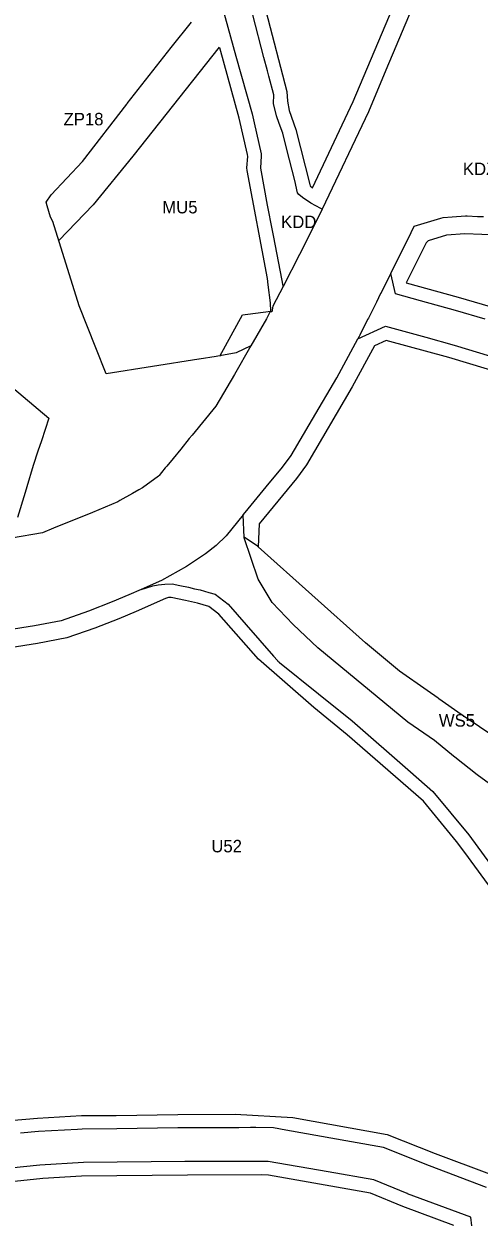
# Model space of a CAD drawing. Extents: x 7428103 to 7431580, y 5545880 to 5549002.
# Drawn here: x 7430015 to 7430217, y 5547123 to 5547655 of the extents above; entities that cross this region are included whole.
import ezdxf

# ---------------------------------------------------------------- set-up
doc = ezdxf.new("R2010")
doc.units = 0
for name, color, linetype in [('CZ_L_linie rozgraniczające tereny o różnym przeznaczeniu oraz różnych warunkach ich zabudowy i zagospodarowania', 7, 'Continuous'), ('CZ_L_maksymalne nieprzekraczalne linie zabudowy', 7, 'Continuous'), ('CZ_L_opisy_linie rozgraniczające tereny o różnym przeznaczeniu oraz różnych warunkach ich zabudowy i zagospodarowania', 7, 'Continuous')]:
    doc.layers.add(name, color=color, linetype=linetype)

msp = doc.modelspace()

# ---------------------------------------------------------------- linework, layer by layer
at = {"layer": 'CZ_L_linie rozgraniczające tereny o różnym przeznaczeniu oraz różnych warunkach ich zabudowy i zagospodarowania'}
for p, q in [((7430103.34, 5547662.02), (7430109.29, 5547640.69)), ((7430121.68, 5547640.08), (7430116.77, 5547658.97)), ((7430187.6, 5547662.03), (7430175.91, 5547634.4)), ((7430080.55, 5547644.47), (7430089.49, 5547655.67)), ((7430060.95, 5547619.6), (7430080.55, 5547644.47)), ((7430109.29, 5547640.69), (7430116.44, 5547615.02)), ((7430123.26, 5547634.11), (7430121.68, 5547640.08)), ((7430123.88, 5547631.75), (7430123.26, 5547634.11)), ((7430126.06, 5547623.49), (7430123.88, 5547631.75)), ((7430175.91, 5547634.4), (7430168.1, 5547615.94)), ((7430126, 5547619.68), (7430126.06, 5547623.49)), ((7430041.12, 5547593.87), (7430060.77, 5547619.36)), ((7430060.77, 5547619.36), (7430060.95, 5547619.6)), ((7430127.35, 5547614.15), (7430126, 5547619.68)), ((7430168.1, 5547615.94), (7430147.61, 5547572.74)), ((7430116.44, 5547615.02), (7430117.37, 5547610.98)), ((7430117.37, 5547610.98), (7430120.5, 5547597.34)), ((7430128.55, 5547610.79), (7430127.35, 5547614.15)), ((7430130.09, 5547606.41), (7430128.55, 5547610.79)), ((7430131.91, 5547599.26), (7430130.09, 5547606.41)), ((7430120.55, 5547596.45), (7430120.13, 5547590.86)), ((7430120.5, 5547597.34), (7430120.43, 5547596.99)), ((7430120.43, 5547596.99), (7430120.43, 5547596.97)), ((7430120.43, 5547596.97), (7430120.44, 5547596.97)), ((7430120.44, 5547596.97), (7430120.55, 5547596.45)), ((7430135.41, 5547585.48), (7430131.91, 5547599.26)), ((7430027.24, 5547579.08), (7430041.12, 5547593.87)), ((7430120.13, 5547590.86), (7430123.18, 5547574.5)), ((7430136.6, 5547579.96), (7430135.41, 5547585.48)), ((7430024.98, 5547575.82), (7430027.24, 5547579.08)), ((7430137.18, 5547579.26), (7430136.6, 5547579.96)), ((7430138.87, 5547577.91), (7430137.18, 5547579.26)), ((7430025.43, 5547574.25), (7430024.98, 5547575.82)), ((7430026.89, 5547569.16), (7430025.43, 5547574.25)), ((7430123.18, 5547574.5), (7430125.32, 5547563.31)), ((7430142.5, 5547575.41), (7430138.87, 5547577.91)), ((7430147.03, 5547573.05), (7430142.5, 5547575.41)), ((7430147.61, 5547572.74), (7430147.03, 5547573.05)), ((7430027.94, 5547567.27), (7430026.89, 5547569.16)), ((7430147.52, 5547572.56), (7430137.52, 5547552.62)), ((7430147.61, 5547572.74), (7430147.52, 5547572.56)), ((7430188.51, 5547565.14), (7430200.32, 5547568.75)), ((7430200.32, 5547568.75), (7430201.34, 5547569.08)), ((7430201.34, 5547569.08), (7430205.32, 5547569.36)), ((7430205.32, 5547569.36), (7430211.26, 5547569.73)), ((7430211.26, 5547569.73), (7430212.04, 5547569.7)), ((7430212.04, 5547569.7), (7430216.64, 5547569.5)), ((7430216.64, 5547569.5), (7430219.19, 5547569.4)), ((7430039.57, 5547529.77), (7430027.94, 5547567.27)), ((7430125.32, 5547563.31), (7430125.77, 5547561.01)), ((7430178.06, 5547544.23), (7430187.15, 5547562.35)), ((7430187.15, 5547562.35), (7430188.51, 5547565.14)), ((7430125.77, 5547561.01), (7430129.64, 5547541.1)), ((7430137.52, 5547552.62), (7430130.18, 5547538.32)), ((7430129.64, 5547541.1), (7430129.98, 5547539.37)), ((7430177.64, 5547543.39), (7430173.59, 5547535.33)), ((7430178.06, 5547544.23), (7430177.64, 5547543.39)), ((7430180.09, 5547535.11), (7430178.06, 5547544.23)), ((7430130.18, 5547538.32), (7430125.71, 5547529.6)), ((7430129.98, 5547539.37), (7430130.18, 5547538.32)), ((7430171.64, 5547531.43), (7430168.11, 5547524.39)), ((7430173.55, 5547535.24), (7430171.64, 5547531.43)), ((7430173.59, 5547535.33), (7430173.55, 5547535.24)), ((7430191.32, 5547532.04), (7430180.09, 5547535.11)), ((7430206.84, 5547527.79), (7430191.32, 5547532.04)), ((7430047, 5547511.09), (7430039.57, 5547529.77)), ((7430124.37, 5547527), (7430122.85, 5547524.03)), ((7430125.28, 5547527.15), (7430124.37, 5547527)), ((7430125.71, 5547529.6), (7430125.28, 5547527.15)), ((7430220.04, 5547523.9), (7430206.84, 5547527.79)), ((7430122.85, 5547524.03), (7430115.96, 5547512.09)), ((7430163.44, 5547515.23), (7430175.64, 5547520.78)), ((7430167.77, 5547523.72), (7430164.31, 5547516.82)), ((7430168.11, 5547524.39), (7430167.77, 5547523.72)), ((7430175.64, 5547520.78), (7430193.68, 5547515.84)), ((7429985, 5547514.47), (7430026.23, 5547479.99)), ((7430154.02, 5547497.86), (7430163.44, 5547515.23)), ((7430164, 5547516.25), (7430163.44, 5547515.23)), ((7430164.31, 5547516.82), (7430164, 5547516.25)), ((7430193.68, 5547515.84), (7430206.19, 5547512.39)), ((7430051.58, 5547499.58), (7430047, 5547511.09)), ((7430115.96, 5547512.09), (7430108.59, 5547499.31)), ((7430115.96, 5547512.09), (7430109.32, 5547508.89)), ((7430206.19, 5547512.39), (7430222.42, 5547507.51)), ((7430092.83, 5547506.16), (7430051.58, 5547499.58)), ((7430092.85, 5547506.17), (7430092.83, 5547506.16)), ((7430092.89, 5547506.15), (7430092.85, 5547506.17)), ((7430092.92, 5547506.17), (7430092.89, 5547506.15)), ((7430100.5, 5547507.35), (7430092.92, 5547506.17)), ((7430109.32, 5547508.89), (7430100.5, 5547507.35)), ((7430108.59, 5547499.31), (7430100.29, 5547485.2)), ((7430143.31, 5547479.44), (7430154.02, 5547497.86)), ((7430100.29, 5547485.2), (7430089.77, 5547472.38)), ((7430026.23, 5547479.99), (7430022.84, 5547469.87)), ((7430133.77, 5547463.35), (7430143.31, 5547479.44)), ((7430089.77, 5547472.38), (7430088.52, 5547470.86)), ((7430022.84, 5547469.87), (7430021.3, 5547465.27)), ((7430088.52, 5547470.86), (7430084.73, 5547466.22)), ((7430021.3, 5547465.27), (7430019.2, 5547458.97)), ((7430081.35, 5547462.11), (7430078.51, 5547458.64)), ((7430084.73, 5547466.22), (7430081.35, 5547462.11)), ((7430129.92, 5547458.25), (7430133.77, 5547463.35)), ((7430019.2, 5547458.97), (7430016.35, 5547449.43)), ((7430076.24, 5547455.87), (7430075.11, 5547454.49)), ((7430077.87, 5547457.85), (7430076.24, 5547455.87)), ((7430078.51, 5547458.64), (7430077.87, 5547457.85)), ((7430122.75, 5547449.52), (7430129.92, 5547458.25)), ((7430074.86, 5547454.17), (7430067.76, 5547449.03)), ((7430075.11, 5547454.49), (7430074.86, 5547454.17)), ((7430015.61, 5547446.97), (7430012.28, 5547435.82)), ((7430016.35, 5547449.43), (7430015.61, 5547446.97)), ((7430063.35, 5547446.56), (7430057.71, 5547443.4)), ((7430066.08, 5547448.09), (7430063.35, 5547446.56)), ((7430067.76, 5547449.03), (7430066.08, 5547448.09)), ((7430113.4, 5547438.12), (7430122.75, 5547449.52)), ((7430056.75, 5547442.87), (7430045.58, 5547438.07)), ((7430057.71, 5547443.4), (7430056.75, 5547442.87)), ((7430045.58, 5547438.07), (7430028.29, 5547431.18)), ((7430112.47, 5547436.99), (7430104.89, 5547427.78)), ((7430112.47, 5547436.99), (7430113.4, 5547438.12)), ((7430112.93, 5547427.01), (7430112.47, 5547436.99)), ((7430028.29, 5547431.18), (7430023.35, 5547429.08)), ((7430023.35, 5547429.08), (7430009.63, 5547426.66)), ((7430104.89, 5547427.78), (7430100.47, 5547423.45)), ((7430112.93, 5547427), (7430112.93, 5547427.01)), ((7430113.08, 5547426.91), (7430112.93, 5547427.01)), ((7430112.94, 5547426.99), (7430112.93, 5547427)), ((7430112.99, 5547426.82), (7430112.94, 5547426.99)), ((7430119.14, 5547408.45), (7430112.99, 5547426.82)), ((7430119.1, 5547422.94), (7430113.08, 5547426.91)), ((7430095.74, 5547419.77), (7430087.35, 5547414.15)), ((7430100.47, 5547423.45), (7430095.74, 5547419.77)), ((7430119.2, 5547422.84), (7430119.1, 5547422.94)), ((7430166.87, 5547380.21), (7430119.2, 5547422.84)), ((7430087.35, 5547414.15), (7430079.89, 5547409.98)), ((7430079.89, 5547409.98), (7430076.27, 5547407.96)), ((7430125.41, 5547398.09), (7430119.14, 5547408.45)), ((7430067.15, 5547403.89), (7430061.74, 5547401.48)), ((7430076.27, 5547407.96), (7430067.15, 5547403.89)), ((7430067.15, 5547403.89), (7430072.3, 5547405.46)), ((7430072.3, 5547405.46), (7430074.77, 5547406.04)), ((7430074.77, 5547406.04), (7430077.62, 5547406.28)), ((7430077.62, 5547406.28), (7430080.9, 5547406.41)), ((7430080.9, 5547406.41), (7430084.4, 5547405.7)), ((7430084.4, 5547405.7), (7430088.14, 5547404.94)), ((7430088.14, 5547404.94), (7430090.9, 5547404.26)), ((7430090.9, 5547404.26), (7430093.42, 5547403.7)), ((7430093.42, 5547403.7), (7430097.23, 5547402.64)), ((7430054.34, 5547398.38), (7430043.74, 5547394.27)), ((7430061.74, 5547401.48), (7430054.34, 5547398.38)), ((7430097.23, 5547402.64), (7430100.05, 5547401.76)), ((7430100.05, 5547401.76), (7430105.8, 5547397.35)), ((7430105.8, 5547397.35), (7430113.83, 5547388.22)), ((7430134.71, 5547388.36), (7430125.41, 5547398.09)), ((7430043.74, 5547394.27), (7430031.71, 5547390.02)), ((7430019.77, 5547387.83), (7430007.67, 5547385.89)), ((7430031.71, 5547390.02), (7430019.77, 5547387.83)), ((7430113.83, 5547388.22), (7430125.97, 5547374.36)), ((7430145.72, 5547378), (7430134.71, 5547388.36)), ((7430185.66, 5547345.08), (7430145.72, 5547378)), ((7430181.99, 5547367.68), (7430166.87, 5547380.21)), ((7430125.97, 5547374.36), (7430127.71, 5547372.37)), ((7430127.71, 5547372.37), (7430127.76, 5547372.32)), ((7430127.76, 5547372.32), (7430127.77, 5547372.31)), ((7430127.77, 5547372.31), (7430128.21, 5547371.86)), ((7430128.21, 5547371.86), (7430128.24, 5547371.83)), ((7430128.24, 5547371.83), (7430128.27, 5547371.8)), ((7430128.27, 5547371.8), (7430128.48, 5547371.64)), ((7430128.48, 5547371.64), (7430128.58, 5547371.53)), ((7430128.58, 5547371.53), (7430128.63, 5547371.5)), ((7430128.63, 5547371.5), (7430128.65, 5547371.47)), ((7430128.65, 5547371.47), (7430145.99, 5547357.53)), ((7430194.27, 5547359.02), (7430181.99, 5547367.68)), ((7430145.99, 5547357.53), (7430160.83, 5547345.6)), ((7430199.07, 5547355.64), (7430194.27, 5547359.02)), ((7430199.37, 5547355.42), (7430199.07, 5547355.64)), ((7430209.31, 5547348.41), (7430199.37, 5547355.42)), ((7430160.83, 5547345.6), (7430186.8, 5547322.93)), ((7430197.45, 5547336.92), (7430185.66, 5547345.08)), ((7430225.58, 5547337.5), (7430209.31, 5547348.41)), ((7430205.94, 5547329.91), (7430197.45, 5547336.92)), ((7430206.53, 5547329.44), (7430205.94, 5547329.91)), ((7430216.48, 5547321.68), (7430206.53, 5547329.44)), ((7430186.8, 5547322.93), (7430196.77, 5547314.22)), ((7430221.93, 5547317.66), (7430216.48, 5547321.68)), ((7430196.77, 5547314.22), (7430212.67, 5547295.01)), ((7430212.67, 5547295.01), (7430267.72, 5547219.77)), ((7430038.89, 5547164.29), (7430021.5, 5547163.32)), ((7430040.91, 5547164.4), (7430038.89, 5547164.29)), ((7430056.37, 5547164.46), (7430040.91, 5547164.31)), ((7430040.91, 5547164.31), (7430040.91, 5547164.4)), ((7430083.49, 5547164.89), (7430056.37, 5547164.46)), ((7430106.93, 5547165.02), (7430083.49, 5547164.89)), ((7430110.54, 5547165.03), (7430106.93, 5547165.02)), ((7430115.8, 5547165.04), (7430110.54, 5547165.03)), ((7430118.16, 5547165.04), (7430115.8, 5547165.04)), ((7430126.03, 5547164.9), (7430118.16, 5547165.04)), ((7430131.42, 5547163.92), (7430126.03, 5547164.9)), ((7430131.5, 5547163.91), (7430131.42, 5547163.92)), ((7430160.59, 5547158.81), (7430131.5, 5547163.91)), ((7430021.5, 5547163.32), (7430013.52, 5547162.58)), ((7430174.76, 5547156.22), (7430160.59, 5547158.81)), ((7430195.21, 5547148.12), (7430174.76, 5547156.22)), ((7430022.14, 5547148.34), (7430001.8, 5547146.27)), ((7430022.15, 5547148.34), (7430022.14, 5547148.34)), ((7430041.51, 5547149.5), (7430022.15, 5547148.34)), ((7430086.51, 5547149.99), (7430041.51, 5547149.5)), ((7430123.64, 5547150.05), (7430086.51, 5547149.99)), ((7430150.25, 5547145.4), (7430123.64, 5547150.05)), ((7430220.62, 5547138.54), (7430195.21, 5547148.12)), ((7430170.52, 5547141.84), (7430150.25, 5547145.4)), ((7430185.37, 5547135.78), (7430170.52, 5547141.84)), ((7430185.45, 5547135.76), (7430185.37, 5547135.78)), ((7430185.52, 5547135.72), (7430185.45, 5547135.76)), ((7430213.66, 5547125.26), (7430185.52, 5547135.72)), ((7430214.07, 5547121.48), (7430213.66, 5547125.26))]:
    msp.add_line(p, q, dxfattribs=at)
at = {"layer": 'CZ_L_maksymalne nieprzekraczalne linie zabudowy'}
for points in [[(7430119.71, 5547669.15), (7430122.51, 5547660.71), (7430131.89, 5547624.92), (7430132.14, 5547620.6), (7430132.97, 5547616.57), (7430135.86, 5547608.04), (7430142.03, 5547583.6), (7430142.27, 5547583.04), (7430143.24, 5547582.19), (7430161.35, 5547620.52), (7430180.46, 5547665.78), (7430185.28, 5547678.67), (7430187.86, 5547687.18), (7430190.24, 5547697.29), (7430191.35, 5547703.01), (7430194.6, 5547724.45), (7430196.19, 5547736.58), (7430196.87, 5547744.92), (7430197.42, 5547759.23), (7430197.41, 5547766.79), (7430197.23, 5547769.37), (7430196.92, 5547771.13), (7430196.44, 5547771.85), (7430152.39, 5547756.12)], [(7430101.88, 5547644.59), (7430063.47, 5547596.31), (7430045.82, 5547574.67), (7430030.56, 5547558.8)], [(7430102.13, 5547507.53), (7430112.25, 5547525.77), (7430114.61, 5547526.14), (7430124.82, 5547527.44), (7430124.62, 5547531.11), (7430123.53, 5547539.06), (7430123.34, 5547541.89), (7430114.22, 5547589.84), (7430114.14, 5547591.03), (7430114.51, 5547596.04), (7430114.41, 5547597.04), (7430110.72, 5547613.15), (7430102.08, 5547644.35)], [(7430226.11, 5547561.1), (7430211.02, 5547561.7), (7430202.87, 5547561.17), (7430194.68, 5547558.66), (7430193.84, 5547557.84), (7430184.91, 5547540.04), (7430207.98, 5547533.69), (7430229.24, 5547527.37)], [(7430503.8, 5547291.55), (7430523.13, 5547319.55), (7430479.33, 5547347.76), (7430459.83, 5547358.75), (7430397.54, 5547398.89), (7430356.88, 5547424.55), (7430322.82, 5547445.42), (7430315.28, 5547450.43), (7430303.09, 5547458.89), (7430279.12, 5547476.32), (7430270.95, 5547481.61), (7430264.96, 5547484.82), (7430254.27, 5547489.3), (7430235.92, 5547496.41), (7430221.07, 5547501.63), (7430203.91, 5547506.8), (7430175.96, 5547514.41), (7430170.84, 5547512.07), (7430160.94, 5547493.84), (7430140.6, 5547459.18), (7430136.14, 5547453.22), (7430119.58, 5547433.04), (7430119.2, 5547422.84)], [(7430263, 5547216.05), (7430210.93, 5547287.22), (7430207.3, 5547292.08), (7430192.53, 5547309.94), (7430158.75, 5547339.45), (7430143.84, 5547351.56), (7430119.24, 5547372.94), (7430101.61, 5547393), (7430097.2, 5547396.36), (7430092.13, 5547397.83), (7430086.89, 5547399.07), (7430080.44, 5547400.38), (7430079.25, 5547400.34), (7430077.93, 5547399.94), (7430064.99, 5547394.17), (7430057.24, 5547390.92), (7430046.61, 5547386.8), (7430034.09, 5547382.38), (7430021.09, 5547379.94), (7430008.92, 5547377.98)], [(7430009.06, 5547168.2), (7430021.11, 5547169.3), (7430040.61, 5547170.39), (7430056.08, 5547170.46), (7430083.44, 5547170.89), (7430108.98, 5547171.03), (7430134.51, 5547169.47), (7430176.45, 5547161.98), (7430197.83, 5547153.55), (7430221.84, 5547144.49)], [(7430206.1, 5547121.66), (7430183.43, 5547130.1), (7430168.99, 5547135.98), (7430123.79, 5547143.94), (7430120.43, 5547144.05), (7430087.76, 5547143.99), (7430040.61, 5547143.44), (7430023.55, 5547142.41), (7430002.37, 5547140.29), (7429976.31, 5547138.05), (7429968.64, 5547137.72), (7429713.38, 5547134.86), (7429639.87, 5547129.69), (7429607.51, 5547127.67)]]:
    msp.add_lwpolyline(points, dxfattribs=at)

# ---------------------------------------------------------------- texts
at = {"layer": 'CZ_L_opisy_linie rozgraniczające tereny o różnym przeznaczeniu oraz różnych warunkach ich zabudowy i zagospodarowania'}
for s, p in [('ZP18', (7430032.71, 5547609.92)), ('KDZ', (7430210.09, 5547587.82)), ('MU5', (7430076.55, 5547570.84)), ('KDD', (7430129.34, 5547564.3)), ('WS5', (7430199.4, 5547343.02)), ('U52', (7430098.34, 5547287.23))]:
    msp.add_text(s, height=5.549, dxfattribs=at).set_placement(p)

doc.saveas('drawing.dxf')
